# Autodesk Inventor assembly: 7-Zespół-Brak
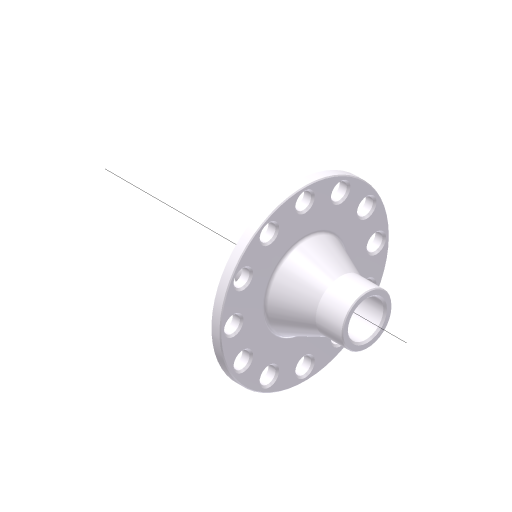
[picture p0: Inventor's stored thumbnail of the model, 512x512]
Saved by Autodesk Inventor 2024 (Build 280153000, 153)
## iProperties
Company: ATC
Shininess: 20.0
Length Units: 11269
Angle Units: 11279
Time Units: 11290
Mass Units: 11283
Length Display Precision: 3
Angle Display Precision: 2
Created: 2023-03
Part Number: 7-Zespół-Brak
Document SubType Name: Assembly
Designer: Andrzej Jaskulski
Checked By: A.J.
Engr Approved By: Andrzej Jaskulski
Mfg Approved By: Andrzej Jaskulski
Authority: A.J.
Density: 0.0
Volumn: 0.0
Area: 0.0
PropertySet Name: Model Information
Control State: 0
Master: False
Checked Out: False
Title: A.J.: Kurs R2024-MEP
Author: Andrzej Jaskulski
Revision Number: 1/24
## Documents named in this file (5)
- C:\Users\AndJas\Documents\R2024-MEP\Obszar roboczy\7-Zespół-Brak.iam
- C:\Users\AndJas\Documents\R2024-MEP\Obszar roboczy\T.ipt
- D:\R5-PPZiC\BRAK1.iam
- D:\R5-PPZiC\BRAK2.iam
- D:\R5-PPZiC\BRAK3.iam
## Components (4 placed, 4 different names)
1. Assembly3.iam:1 [sub-assembly]
2. Assembly2.iam:1 [sub-assembly]
3. Tuleja
4. Assembly1.iam:1 [sub-assembly]
